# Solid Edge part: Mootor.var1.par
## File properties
Author: jaanm
Template: ansi metric part.par
Last saved by: jaanm
Revision: 13
Application: Solid Edge
Accuracy: 0,990
Face Style: Model Default
Coef. of Thermal Exp: 0.0
Thermal Conductivity: 0.0
Specific Heat: 0.0
Modulus of Elasticity: 0.0
Poisson's Ratio: 0.0
Yield Stress: 0.0
Ultimate Stress: 0.0
Elongation: 0.0
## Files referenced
..\Lendavkaru.asm
C:\Users\jaanm\Google Drive\Ained2016\3dmodel\Lendav käru\Tiib.var1.par
ru\Lendavkaru.asm
ru\Tiib.var1.par
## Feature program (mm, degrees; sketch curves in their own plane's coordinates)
sketch for "unnamed Protrusion 1" plane through (0, 0, 0) normal (0, -1, 0) x-axis (1, 0, 0)
  circle centre (0, 0) radius 125
extrude "unnamed Protrusion 1" add finite 400 along -normal
thinwall "Thinwall_1"  Thickness = 10 mm
sketch for "unnamed Cutout 1" plane through (0, 400, 0) normal (0, 1, 0) x-axis (0, 0, 1)
  circle centre (0, 0) radius 100
extrude "unnamed Cutout 1" cut to key point along -normal
chamfer "Chamfer_1" setback 5
chamfer "Chamfer_2" setback 5
sketch for "ExtrudedProtrusion_2" plane through (-115, 0, 0) normal (1, 0, 0) x-axis (0, 1, 0)
  line (36.3224, -7.5) -> (336.3224, -7.5)
  line (336.3224, -7.5) -> (336.3224, 7.5)
  line (336.3224, 7.5) -> (36.3224, 7.5)
  line (36.3224, 7.5) -> (36.3224, -7.5)
extrude "ExtrudedProtrusion_2" add finite 70 along -normal
draft "Draft_2"  Angles1 = 20 deg
pattern "unnamed Pattern 1" of "Draft_2", "ExtrudedProtrusion_2"
extrude "unnamed Protrusion 2" add finite 70
draft "unnamed Draft 1"
extrude "unnamed Protrusion 3" add finite 70
draft "unnamed Draft 2"
extrude "unnamed Protrusion 4" add finite 70
draft "unnamed Draft 3"
extrude "unnamed Protrusion 5" add finite 70
draft "unnamed Draft 4"
extrude "unnamed Protrusion 6" add finite 70
draft "unnamed Draft 5"
extrude "unnamed Protrusion 7" add finite 70
draft "unnamed Draft 6"
extrude "unnamed Protrusion 8" add finite 70
draft "unnamed Draft 7"
extrude "unnamed Protrusion 9" add finite 70
draft "unnamed Draft 8"
extrude "unnamed Protrusion 10" add finite 70
draft "unnamed Draft 9"
extrude "unnamed Protrusion 11" add finite 70
draft "unnamed Draft 10"
extrude "unnamed Protrusion 12" add finite 70
draft "unnamed Draft 11"
extrude "unnamed Protrusion 13" add finite 70
draft "unnamed Draft 12"
extrude "unnamed Protrusion 14" add finite 70
draft "unnamed Draft 13"
extrude "unnamed Protrusion 15" add finite 70
draft "unnamed Draft 14"
sketch for "ExtrudedProtrusion_22" plane through (-169.0059, 186.3224, 75.2463) normal (-0.913545, 0, 0.406737) x-axis (0, 1, 0)
  line (-150, -7.5) -> (150, -7.5)
  line (150, -7.5) -> (150, 7.5)
  line (150, 7.5) -> (-150, 7.5)
  line (-150, 7.5) -> (-150, -7.5)
extrude "ExtrudedProtrusion_22" add finite 50 along +normal
draft "Draft_23"  Angles1 = 5 deg
sketch for "ExtrudedProtrusion_23" plane through (-224.5853, 186.3224, 91.782) normal (-0.406737, 0, -0.913545) x-axis (0, 1, 0)
  line (150, -46.4162) -> (150, 7.5)
  line (150, 7.5) -> (-150, 7.5)
  line (-150, 7.5) -> (-150, -46.4162)
  line (-150, -46.4162) -> (150, -46.4162)
extrude "ExtrudedProtrusion_23" add finite 65 along -normal
sketch for "ExtrudedProtrusion_24" plane through (-224.5853, 186.3224, 91.782) normal (-0.406737, 0, -0.913545) x-axis (0, 1, 0)
  line (150, -46.4162) -> (150, 7.5)
  line (150, 7.5) -> (-150, 7.5)
  line (-150, 7.5) -> (-150, -46.4162)
  line (-150, -46.4162) -> (150, -46.4162)
extrude "ExtrudedProtrusion_24" add finite 50 along +normal
sketch for "Hole_1" plane through (-263.9381, 186.3224, 117.5128) normal (-0.913545, 0, 0.406737) x-axis (0.406737, 0, 0.913545)
  hole centre (-31.1276, 125) bore radius 5
  dimension = 5
  dimension (linear) = 31.1276
  dimension (linear) = 31.1276
hole "Hole_1" diameter 10 through
pattern "unnamed Pattern 2" of "Hole_1"
hole "unnamed Hole 1" through
hole "unnamed Hole 2" through
hole "unnamed Hole 3" through
hole "unnamed Hole 4" through
hole "unnamed Hole 5" through
hole "unnamed Hole 6" through
hole "unnamed Hole 7" through
hole "unnamed Hole 8" through
hole "unnamed Hole 9" through
hole "unnamed Hole 10" through
hole "unnamed Hole 11" through
hole "unnamed Hole 12" through
hole "unnamed Hole 13" through
hole "unnamed Hole 14" through
hole "unnamed Hole 15" through
multibody boolean "unnamed MultibodyBoolean 1"
rib "Rib_1"  Thickness = 15 mm
logasc func "Lip_Groove_1"  LipOrGrooveWidth = 3 mm; LipOrGrooveHeight = 6 mm
sketch for "ExtrudedProtrusion_26" plane through (0, 0, 0) normal (0, -1, 0) x-axis (0, 0, -1)
  circle centre (0, 0) radius 110
extrude "ExtrudedProtrusion_26" add finite 10 along -normal
smart boss "MountingBoss_3"  BossDiameter = 6.35 mm; MountingHoleDiameter = 3.175 mm; MountingHoleDepth = 12.7 mm; RibThickness = 3.175 mm; RibExtent = 100 mm; RibCount = 8; BossDraftAngle = 2 deg; FilletRadius = 1.27 mm; Plane_Distance = 250 mm
smart boss group feature "unnamed SMartBossGroupFeature 1"
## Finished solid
Body 1: solid body, 10 faces, 15 edges, 7 vertices.
  Faces by surface: spline 5, plane 3, cylinder 2
  Edges by curve: circle 5, spline 5, curve on surface 4, line 1
Body 2: solid body, 246 faces, 556 edges, 298 vertices, 2 separate solids.
  Faces by surface: plane 220, cylinder 21, cone 3, spline 2
  Edges by curve: line 416, ellipse 80, circle 33, intersection 26, spline 1
Bounding box of the edges (mm; curved faces can reach further): 826.286 x 760.621 x 1492.153, from (-643.7693, -250, -981.7923) to (182.5166, 510.621, 510.3607).
Cylindrical faces by radius (mm): R5 x18, R33.9209 x1, R100 x1, R110 x1, R115 x1, R125 x1
Conical faces (half-angle, radius in mm at the cone's reference point): 45 deg R115 x1, 45 deg R120 x1, 45 deg R125 x1
Planar faces by outward normal: +x 3, +y 4, +z 3, -x 4, -y 6, -z 3, oblique 200
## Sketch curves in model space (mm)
circle centre (0, 0, 0) radius 5
circle centre (0, 0, 0) radius 110
circle centre (0, 400, 0) radius 100
line (-266.9886, 336.3224, 110.6612) -> (-217.7337, 336.3224, 88.7315)
line (-217.7337, 336.3224, 88.7315) -> (-217.7337, 36.3224, 88.7315)
line (-217.7337, 36.3224, 88.7315) -> (-266.9886, 36.3224, 110.6612)
line (-266.9886, 36.3224, 110.6612) -> (-266.9886, 336.3224, 110.6612)
line (-165.9554, 336.3224, 82.0979) -> (-172.0564, 336.3224, 68.3947)
line (-172.0564, 336.3224, 68.3947) -> (-172.0564, 36.3224, 68.3947)
line (-172.0564, 36.3224, 68.3947) -> (-165.9554, 36.3224, 82.0979)
line (-165.9554, 36.3224, 82.0979) -> (-165.9554, 336.3224, 82.0979)
line (-115, 336.3224, -7.5) -> (-115, 336.3224, 7.5)
line (-115, 336.3224, 7.5) -> (-115, 36.3224, 7.5)
line (-115, 36.3224, 7.5) -> (-115, 36.3224, -7.5)
line (-115, 36.3224, -7.5) -> (-115, 336.3224, -7.5)
circle centre (0, 0, 0) radius 125
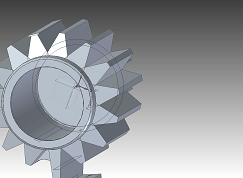
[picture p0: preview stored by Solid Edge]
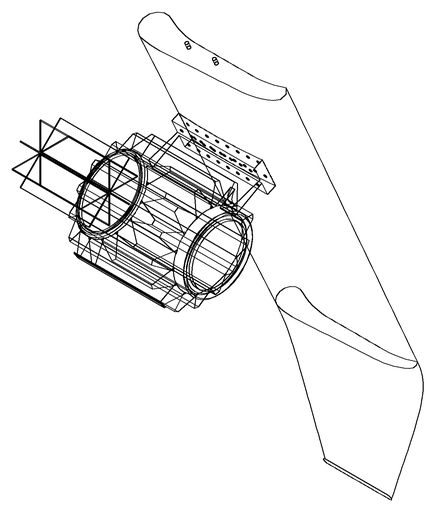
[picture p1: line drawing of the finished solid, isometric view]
